// Mitsubishi GX Works2 project: 定时中断   PLC: FX3U/FX3UC

PROGRAM MAIN
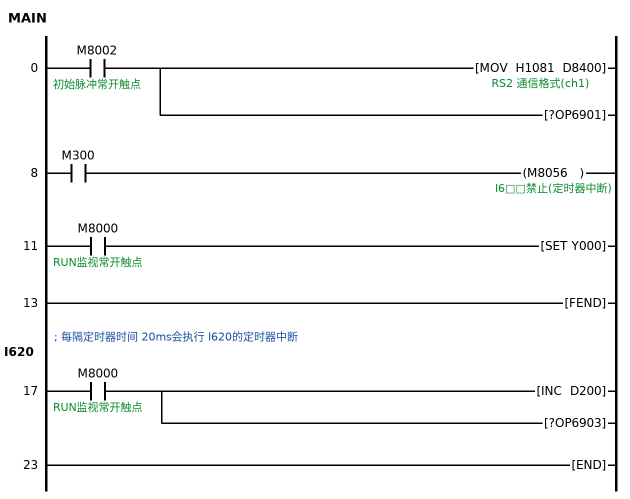
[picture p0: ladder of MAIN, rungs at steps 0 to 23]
0     LD      M8002  ; 初始脉冲常开触点
      MOV     H1081 D8400  ; RS2 通信格式(ch1)
      ?OP6901
        [note] 允许中断
8     LD      M300
      OUT     M8056  ; I6□□禁止(定时器中断)
11    LD      M8000  ; RUN监视常开触点
      SET     Y000
13    FEND
        [note] 主程序结束
      I620
; 每隔定时器时间 20ms会执行 I620的定时器中断
17    LD      M8000  ; RUN监视常开触点
      INC     D200
      ?OP6903
        [note] 中断返回
23    END
END_PROGRAM

// device comments not shown above
C10  ; CCD1拍照连续不良计数
C11  ; CCD2连续不良计数
